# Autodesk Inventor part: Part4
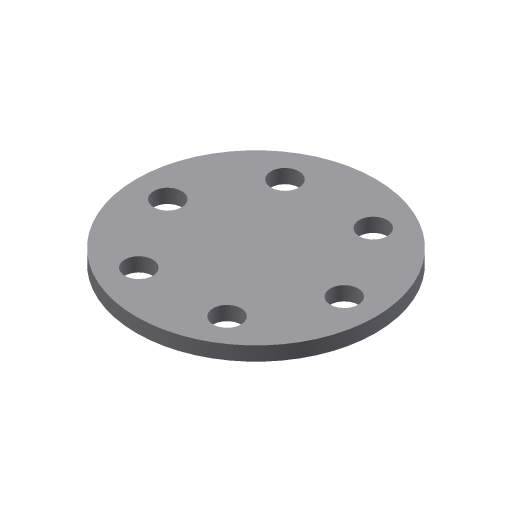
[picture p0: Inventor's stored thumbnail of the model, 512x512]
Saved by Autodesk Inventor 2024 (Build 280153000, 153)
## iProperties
Created: 2008-05
Part Number: Part4
Document SubType Name: Modeling
Designer: CADCIM
Density: 1 g/cm^3
Material: Generic
Appearance: Default
Author: CADCIM
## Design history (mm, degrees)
sketch "Sketch1"
  geometry: C1 r 17 at (0, 0)
  constraints: 1 centre point, 1 other
  dimensions: "d12" = 34 diameter of C1
extrude "Extrusion1" new body sketch "Sketch1" distance "d0" = 2; taper "d1" = 0 deg
sketch "Sketch2"
  geometry: 1 further point
hole "Hole1" sketch "Sketch2" at (5.9, 10.769) diameter "d2" = 4; stored, may be unused: countersink angle "d6" = 90 deg, drill point angle "d8" = 118 deg; dims "d3" = 6, "d4" = 4, "d5" = 2, "d7" = 8
pattern_circular "Circular Pattern1" dims angle "d10" = 360 deg
body "Solid1"
